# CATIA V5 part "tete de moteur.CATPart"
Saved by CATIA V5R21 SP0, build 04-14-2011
Part number: tete de moteur
Material "Aluminium": density 2710 kg/m3, Young's modulus 7e+10 Pa, Poisson ratio 0.346, thermal expansion 2.36e-05 1/K
Bounding box of the stored display mesh (mm): x -16.989 to 17.003, y -17.05 to 17.05, z 0 to 13.5
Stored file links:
  C:\Users\Olivier\Desktop\redaction CATIA (local)\CATIA\DONNEES\Exercice mise en plan 2 (Pompe de ventilation)\Pompe de ventilation (Product inclus)\tete de moteur.CATPart
  C:\Users\Olivier\Desktop\redaction TBM CATIA\pompe à moteur de ventilation refait\engine block.CATPart
  C:\Program Files\Dassault Systemes\B21\win_b64\startup\materials\French\Catalog.CATMaterial
  C:\Program Files\Dassault Systemes\B21\win_b64\resources\graphic\figures\CATIA_EnvironmentMap_Hall_512x512.jpg
  C:\Users\Olivier\Desktop\redaction CATIA (local)\CATIA\DONNEES\Exercice mise en plan 2 (Pompe de ventilation)\Pompe de ventilation (Product inclus)\CATIA_EnvironmentMap_DSBlack_512x512.jpg
  C:\Program Files\Dassault Systemes\B21\win_b64\resources\graphic\figures\CATIA_EnvironmentMap_GridSpot_512x512.jpg
  C:\Program Files\Dassault Systemes\B21\win_b64\resources\graphic\figures\CATIA_EnvironmentMap_NonLinear_512x512.jpg
  C:\Program Files\Dassault Systemes\B21\win_b64\resources\graphic\figures\CATIA_EnvironmentMap_Square2_512x512.jpg
  C:\Users\Olivier\Desktop\redaction CATIA (local)\pompe à moteur de ventilation refait\Pompe_a_moteur_de_ventilation.CATProduct
  C:\Users\Olivier\Desktop\redaction CATIA (local)\pompe à moteur de ventilation refait\Ecrou a collerette M5.CATPart
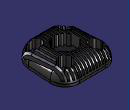
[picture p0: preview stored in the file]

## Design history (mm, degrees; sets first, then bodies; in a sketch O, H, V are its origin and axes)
Body1 (main body), material "Aluminium"
  Sketch1 on xy-plane, origin (0, 0, 0), H (1, 0, 0), V (0, 1, 0)
    point P1 (0, 0)
    point P2 (0, 1.25)
    point P3 (0, -12.5)
    arc A1 centre (-8.2069, 8.2501) radius 8.7999 from (-8.2068, 17.05) to (-16.9887, 7.686) ccw
    line L1 (-16.9887, 7.686) -> (-16.0612, -6.755)
    arc A2 centre (-5.0839, -6.0501) radius 10.9999 from (-16.0612, -6.755) to (-5.0838, -17.05) ccw
    line L2 (-5.0838, -17.05) -> (5.0898, -17.05)
    arc A3 centre (5.0899, -6.0501) radius 10.9999 from (5.0898, -17.05) to (16.0668, -6.7614) ccw
    line L3 (16.0668, -6.7614) -> (17.0027, 7.6809)
    arc A4 centre (8.2212, 8.2501) radius 8.7999 from (17.0027, 7.6809) to (8.2211, 17.05) ccw
    line L4 (8.2211, 17.05) -> (-8.2068, 17.05)
    distance L4 L2 = 34.1
    distance L4 H = 17.05
  Pad1: profile Sketch1, direction (0, 0, 1), length 13.5
  Fillet1: radius 8, on edge [face of Pad1 from Sketch1.L1 | end face of Pad1]
  Sketch2 on zx-plane, origin (0, 0, 0), H (-1, 0, 0), V (0, 0, 1)
    line L1 (0.5, 15.593) -> (0.5, 6.7271)
    point P1 (0.5, 6.7271)
    point P2 (1.5, 6.7271)
    line L2 (1.5, 15.593) -> (1.5, 6.7271)
    line L3 (0.5, 6.7271) -> (1.5, 6.7271)
    line L4 (0.5, 15.593) -> (1.5, 15.593)
    point P5 (1.5, 15.593)
    point P6 (0.5, 15.593)
    point P7 (2.5, 6.7271)
    point P8 (3.5, 6.7271)
    point P9 (3.5, 15.593)
    point P10 (2.5, 15.593)
    line L5 (2.5, 15.593) -> (2.5, 6.7271)
    line L6 (3.5, 15.593) -> (3.5, 6.7271)
    line L7 (2.5, 6.7271) -> (3.5, 6.7271)
    line L8 (2.5, 15.593) -> (3.5, 15.593)
    point P11 (4.5, 6.7271)
    point P12 (5.5, 6.7271)
    point P13 (5.5, 15.593)
    point P14 (4.5, 15.593)
    line L9 (4.5, 15.593) -> (4.5, 6.7271)
    line L10 (5.5, 15.593) -> (5.5, 6.7271)
    line L11 (4.5, 6.7271) -> (5.5, 6.7271)
    line L12 (4.5, 15.593) -> (5.5, 15.593)
    point P15 (6.5, 6.7271)
    point P16 (7.5, 6.7271)
    point P17 (7.5, 15.593)
    point P18 (6.5, 15.593)
    line L13 (6.5, 15.593) -> (6.5, 6.7271)
    line L14 (7.5, 15.593) -> (7.5, 6.7271)
    line L15 (6.5, 6.7271) -> (7.5, 6.7271)
    line L16 (6.5, 15.593) -> (7.5, 15.593)
    point P19 (8.5, 6.7271)
    point P20 (9.5, 6.7271)
    point P21 (9.5, 15.593)
    point P22 (8.5, 15.593)
    line L17 (8.5, 15.593) -> (8.5, 6.7271)
    line L18 (9.5, 15.593) -> (9.5, 6.7271)
    line L19 (8.5, 6.7271) -> (9.5, 6.7271)
    line L20 (8.5, 15.593) -> (9.5, 15.593)
    point P23 (10.5, 6.7271)
    point P24 (11.5, 6.7271)
    point P25 (11.5, 15.593)
    point P26 (10.5, 15.593)
    line L21 (10.5, 15.593) -> (10.5, 6.7271)
    line L22 (11.5, 15.593) -> (11.5, 6.7271)
    line L23 (10.5, 6.7271) -> (11.5, 6.7271)
    line L24 (10.5, 15.593) -> (11.5, 15.593)
    point P27 (12.5, 6.7271)
    point P28 (13.5, 6.7271)
    point P29 (13.5, 15.593)
    point P30 (12.5, 15.593)
    line L25 (12.5, 15.593) -> (12.5, 6.7271)
    line L26 (13.5, 15.593) -> (13.5, 6.7271)
    line L27 (12.5, 6.7271) -> (13.5, 6.7271)
    line L28 (12.5, 15.593) -> (13.5, 15.593)
    point P31 (14.5, 6.7271)
    point P32 (15.5, 6.7271)
    point P33 (15.5, 15.593)
    point P34 (14.5, 15.593)
    line L29 (14.5, 15.593) -> (14.5, 6.7271)
    line L30 (15.5, 15.593) -> (15.5, 6.7271)
    line L31 (14.5, 6.7271) -> (15.5, 6.7271)
    line L32 (14.5, 15.593) -> (15.5, 15.593)
    point P35 (-0.5, 6.7271)
    point P36 (-1.5, 6.7271)
    point P37 (-1.5, 15.593)
    point P38 (-0.5, 15.593)
    point P39 (-2.5, 6.7271)
    point P40 (-3.5, 6.7271)
    point P41 (-3.5, 15.593)
    point P42 (-2.5, 15.593)
    point P43 (-4.5, 6.7271)
    point P44 (-5.5, 6.7271)
    point P45 (-5.5, 15.593)
    point P46 (-4.5, 15.593)
    point P47 (-6.5, 6.7271)
    point P48 (-7.5, 6.7271)
    point P49 (-7.5, 15.593)
    point P50 (-6.5, 15.593)
    point P51 (-8.5, 6.7271)
    point P52 (-9.5, 6.7271)
    point P53 (-9.5, 15.593)
    point P54 (-8.5, 15.593)
    point P55 (-10.5, 6.7271)
    point P56 (-11.5, 6.7271)
    point P57 (-11.5, 15.593)
    point P58 (-10.5, 15.593)
    point P59 (-12.5, 6.7271)
    point P60 (-13.5, 6.7271)
    point P61 (-13.5, 15.593)
    point P62 (-12.5, 15.593)
    point P63 (-14.5, 6.7271)
    point P64 (-15.5, 6.7271)
    point P65 (-15.5, 15.593)
    point P66 (-14.5, 15.593)
    line L33 (-0.5, 15.593) -> (-0.5, 6.7271)
    line L34 (-1.5, 15.593) -> (-1.5, 6.7271)
    line L35 (-0.5, 6.7271) -> (-1.5, 6.7271)
    line L36 (-0.5, 15.593) -> (-1.5, 15.593)
    line L37 (-2.5, 15.593) -> (-2.5, 6.7271)
    line L38 (-3.5, 15.593) -> (-3.5, 6.7271)
    line L39 (-2.5, 6.7271) -> (-3.5, 6.7271)
    line L40 (-2.5, 15.593) -> (-3.5, 15.593)
    line L41 (-4.5, 15.593) -> (-4.5, 6.7271)
    line L42 (-5.5, 15.593) -> (-5.5, 6.7271)
    line L43 (-4.5, 6.7271) -> (-5.5, 6.7271)
    line L44 (-4.5, 15.593) -> (-5.5, 15.593)
    line L45 (-6.5, 15.593) -> (-6.5, 6.7271)
    line L46 (-7.5, 15.593) -> (-7.5, 6.7271)
    line L47 (-6.5, 6.7271) -> (-7.5, 6.7271)
    line L48 (-6.5, 15.593) -> (-7.5, 15.593)
    line L49 (-8.5, 15.593) -> (-8.5, 6.7271)
    line L50 (-9.5, 15.593) -> (-9.5, 6.7271)
    line L51 (-8.5, 6.7271) -> (-9.5, 6.7271)
    line L52 (-8.5, 15.593) -> (-9.5, 15.593)
    line L53 (-10.5, 15.593) -> (-10.5, 6.7271)
    line L54 (-11.5, 15.593) -> (-11.5, 6.7271)
    line L55 (-10.5, 6.7271) -> (-11.5, 6.7271)
    line L56 (-10.5, 15.593) -> (-11.5, 15.593)
    line L57 (-12.5, 15.593) -> (-12.5, 6.7271)
    line L58 (-13.5, 15.593) -> (-13.5, 6.7271)
    line L59 (-12.5, 6.7271) -> (-13.5, 6.7271)
    line L60 (-12.5, 15.593) -> (-13.5, 15.593)
    line L61 (-14.5, 15.593) -> (-14.5, 6.7271)
    line L62 (-15.5, 15.593) -> (-15.5, 6.7271)
    line L63 (-14.5, 6.7271) -> (-15.5, 6.7271)
    line L64 (-14.5, 15.593) -> (-15.5, 15.593)
    distance L2 L1 = 1
    distance L1 V = 0.5
    vertical: L1 V
    horizontal: L3 H, L4 H
    symmetry: P1 P35 V, P2 P36 V, P5 P37 V, P6 P38 V, P7 P39 V, P8 P40 V, P9 P41 V, P10 P42 V, P11 P43 V, P12 P44 V, P13 P45 V, P14 P46 V, P15 P47 V, P16 P48 V, P17 P49 V, P18 P50 V, P19 P51 V, P20 P52 V, P21 P53 V, P22 P54 V, P23 P55 V, P24 P56 V, P25 P57 V, P26 P58 V, P27 P59 V, P28 P60 V, P29 P61 V, P30 P62 V, P31 P63 V, P32 P64 V, P33 P65 V, P34 P66 V, L1 L33 V, L2 L34 V, L3 L35 V, L4 L36 V, L5 L37 V, L6 L38 V, L7 L39 V, L8 L40 V, L9 L41 V, L10 L42 V, L11 L43 V, L12 L44 V, L13 L45 V, L14 L46 V, L15 L47 V, L16 L48 V, L17 L49 V, L18 L50 V, L19 L51 V, L20 L52 V, L21 L53 V, L22 L54 V, L23 L55 V, L24 L56 V, L25 L57 V, L26 L58 V, L27 L59 V, L28 L60 V, L29 L61 V, L30 L62 V, L31 L63 V, L32 L64 V
  Pocket1: profile Sketch2, direction (0, -1, 0), length 18.5, mirrored extent
  Sketch3 on start face of Pad1, origin (0, 0, 0), H (1, 0, 0), V (0, -1, 0)
    circle A1 centre (0, 0) radius 6.5
    circle A2 centre (0, 0) radius 3
    arc A3 centre (-7.3863, -7.4252) radius 7.9198 from (-15.2898, -6.9174) to (-7.3861, -15.345) ccw
    line L1 (-15.2898, -6.9174) -> (-14.4551, 6.0795)
    arc A4 centre (-4.5756, 5.4452) radius 9.8998 from (-4.5754, 15.345) to (-14.4551, 6.0795) ccw
    line L2 (-4.5754, 15.345) -> (4.5808, 15.345)
    arc A5 centre (4.581, 5.4452) radius 9.8998 from (14.4601, 6.0852) to (4.5808, 15.345) ccw
    line L3 (14.4601, 6.0852) -> (15.3024, -6.9128)
    arc A6 centre (7.3992, -7.4252) radius 7.9198 from (7.399, -15.345) to (15.3024, -6.9128) ccw
    line L4 (7.399, -15.345) -> (-7.3861, -15.345)
    circle A7 centre (0, 0) radius 10.5
  MultiPocket1: profile Sketch3, domains (length 3.5; length 0; length 4; length 14; length 3.5)
  Sketch4 on face of Pocket1 from Sketch2.L27, origin (0, 0, 6.7271), H (1, 0, 0), V (0, 1, 0)
    circle A1 centre (9.545, 9.545) radius 1.5
    point P1 (9.545, 9.545)
    point P2 (-9.545, 9.545)
    distance P1 V = 9.545
    distance P1 H = 9.545
    radius A1 = 1.5
  Sketch5 on face of Pocket1, origin (0, 0, 6.7271), H (1, 0, 0), V (0, 1, 0)
    circle A1 centre (0, 0) radius 7
    radius A1 = 7
  Pocket2: profile Sketch5, direction (0, 0, -1), length 0, opposite side through (limit type 3)
  Sketch6 on face of Pocket2, origin (0, 0, 6.7271), H (1, 0, 0), V (0, 1, 0)
    circle A1 centre (9.545, 9.545) radius 4
    point P1 (9.545, 9.545)
    reference projected circle E1 centre (9.545, 9.545) radius 1.5 from Sketch4.A1
    radius A1 = 4
    concentricity: P1 E1
  Pocket3: profile Sketch6, direction (0, 0, 1), through (limit type 3)
  Pocket4: profile Sketch4, direction (0, 0, -1), through (limit type 3)
  RectPattern1: of Pocket3, Pocket4, Sketch4, direction 1 instances 2, spacing 19.09, along X axis reversed, direction 2 instances 2, spacing 19.09, along Y axis reversed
